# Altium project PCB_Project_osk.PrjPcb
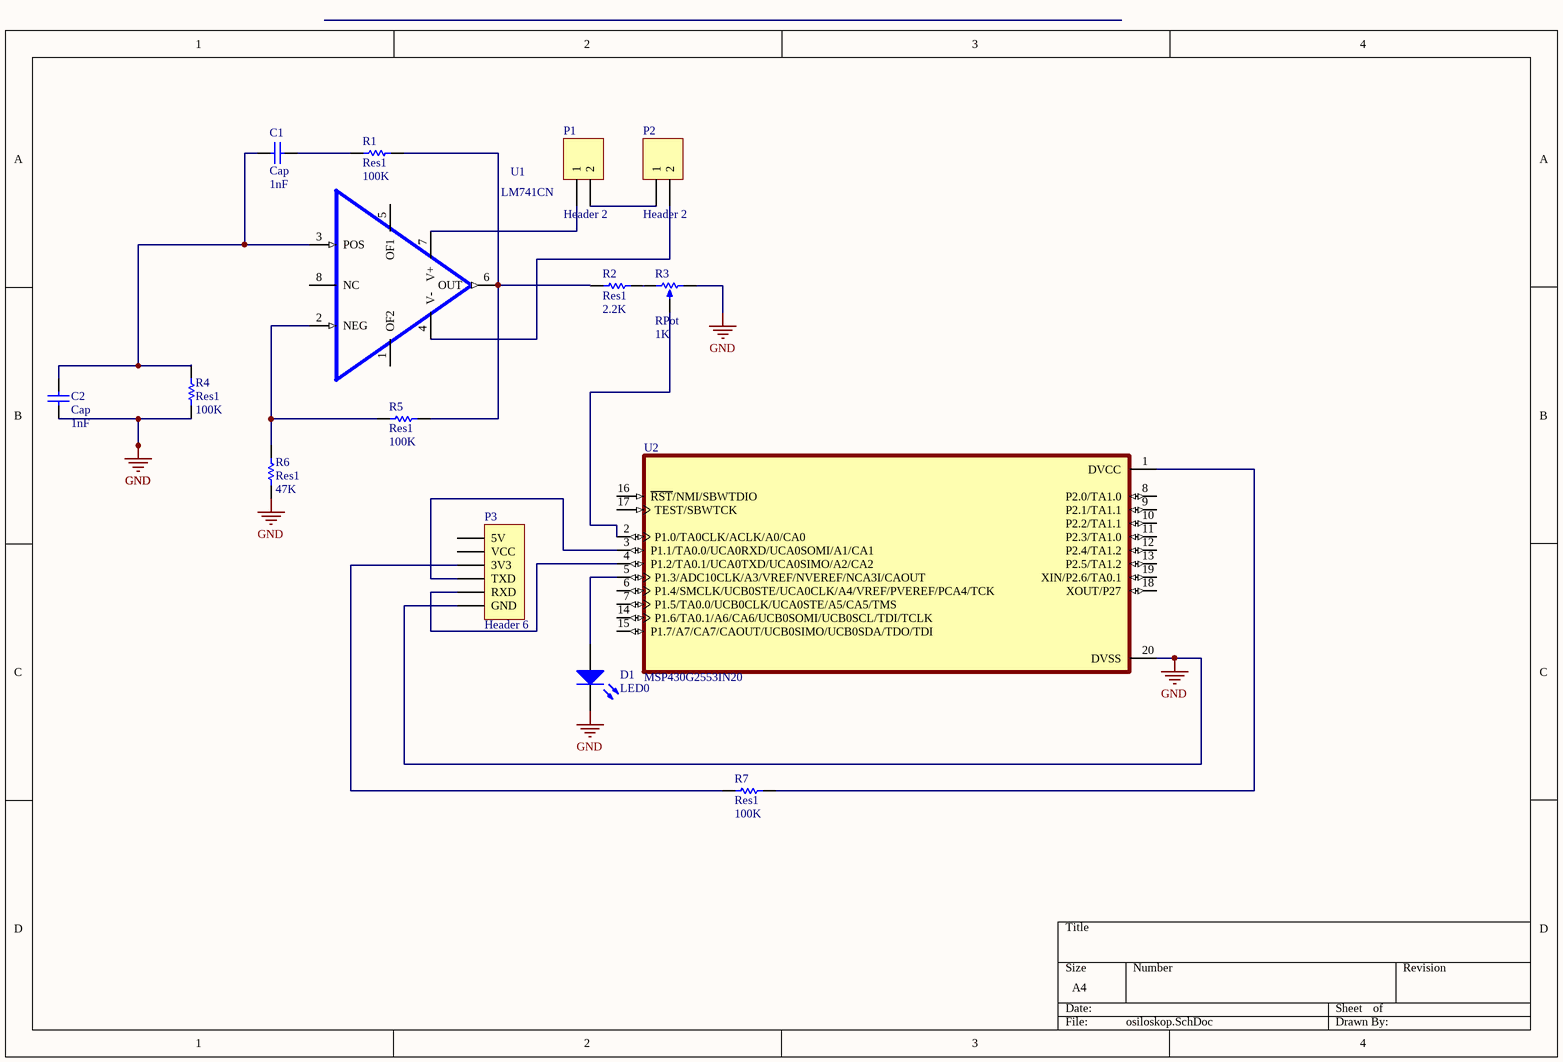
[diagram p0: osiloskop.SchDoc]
1 sheet, 15 parts. Net scope: global (net labels, ports and power ports of the same name join across sheets).
Board file: osk1.PcbDoc

## Sheet osiloskop.SchDoc
size A4; SheetNumber: 1; SheetTotal: 1

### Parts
C1  Cap  value 1nF  [RAD-0.3]
C2  Cap  value 1nF  [RAD-0.3]
D1  LED0  [LED-0]
P1  Header 2  [HDR1X2]
P2  Header 2  [HDR1X2]
P3  Header 6  [HDR1X6]
R1  Res1  value 100K  [AXIAL-0.3]
R2  Res1  value 2.2K  [AXIAL-0.3]
R3  RPot  value 1K  [VR5]
R4  Res1  value 100K  [AXIAL-0.3]
R5  Res1  value 100K  [AXIAL-0.3]
R6  Res1  value 47K  [AXIAL-0.3]
R7  Res1  value 100K  [AXIAL-0.3]
U1  LM741CN  [DIP254P762X508-8]
U2  MSP430G2553IN20  [DIP794W45P254L2692H508Q20]

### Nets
GND: C2.1 D1.2(K) P3.6(GND) R3.2(BOT) R4.1 R6.2 U2.20(DVSS)
NetC1_1: C1.1 R1.2
NetC1_2: C1.2 C2.2 R4.2 U1.3(POS)
NetD1_1: D1.1(A) U2.5(P1.3/ADC10CLK/A3/VREF/NVEREF/NCA3I/CAOUT)
NetP1_1: P1.1 U1.7(V+)
NetP1_2: P1.2 P2.1
NetP2_2: P2.2 U1.4(V-)
NetP3_3: P3.3(3V3) R7.2
NetP3_4: P3.4(TXD) U2.3(P1.1/TA0.0/UCA0RXD/UCA0SOMI/A1/CA1)
NetP3_5: P3.5(RXD) U2.4(P1.2/TA0.1/UCA0TXD/UCA0SIMO/A2/CA2)
NetR1_1: R1.1 R2.1 R5.1 U1.6(OUT)
NetR2_2: R2.2 R3.1(TOP)
NetR3_3: R3.3(TAP) U2.2(P1.0/TA0CLK/ACLK/A0/CA0)
NetR5_2: R5.2 R6.1 U1.2(NEG)
NetR7_1: R7.1 U2.1(DVCC)

Not connected (* = marked no-connect by the designer): P3 1(5V) 2(VCC); U1 1(OF2) 5(OF1) 8(NC); U2 6(P1.4/SMCLK/UCB0STE/UCA0CLK/A4/VREF/PVEREF/PCA4/TCK) 7(P1.5/TA0.0/UCB0CLK/UCA0STE/A5/CA5/TMS) 8(P2.0/TA1.0) 9(P2.1/TA1.1) 10(P2.2/TA1.1) 11(P2.3/TA1.0) 12(P2.4/TA1.2) 13(P2.5/TA1.2) 14(P1.6/TA0.1/A6/CA6/UCB0SOMI/UCB0SCL/TDI/TCLK) 15(P1.7/A7/CA7/CAOUT/UCB0SIMO/UCB0SDA/TDO/TDI) 16(~{RST}/NMI/SBWTDIO) 17(TEST/SBWTCK) 18(XOUT/P27) 19(XIN/P2.6/TA0.1)

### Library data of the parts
C1 C2 = Cap: Capacitor
D1 = LED0: Typical INFRARED GaAs LED
P1 P2 = Header 2: Header, 2-Pin
P3 = Header 6: Header, 6-Pin
R1 R2 R4-R7 = Res1: Resistor
R3 = RPot: Potentiometer; Sim Note: Enter the Resistance value and the set point into parameter fields.; Set Position: 0.5
U1 = LM741CN: General Purpose Amplifier 1 Circuit 8-DIP; MF: ON Semiconductor
U2 = MSP430G2553IN20: MSP430G2x53, MSP430G2x13 Mixed Signal Microcontroller 20-PDIP -40 to 85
